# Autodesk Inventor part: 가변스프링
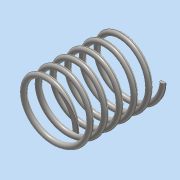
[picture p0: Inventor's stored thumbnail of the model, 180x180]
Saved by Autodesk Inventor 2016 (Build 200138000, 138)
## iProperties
Created: 2018-11
Part Number: 가변스프링
Material: 스테인레스 스틸
Document SubType Name: Modeling
Designer: 공506_39
Density: 8 g/cm^3
Appearance: 반연마
Mass: 84.1985 g
Surface Area: 106.476 cm^2
Volume: 10.5248 cm^3
Author: 공506_39
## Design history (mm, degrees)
sketch "스케치2"
  geometry: L1 (0, 0)-(22.5, 0); L2 (22.5, 0)-(22.5, 67.25); L3 (22.5, 67.25)-(0, 67.25); L4 (0, 67.25)-(0, 0); C1 r 2 at (22.5, 0)
  constraints: 8 end point, 2 parallel, 1 centre point, 1 coincident, 1 horizontal, 1 perpendicular
  dimensions: "d11" = 67.25 distance of L3.end L1.start (derived); "d12" = 45 diameter of L2 L4; "d13" = 4 diameter of C1
feature "코일2" sketch "스케치2" pitch "d14" = 10; turns "d16" = 6; dims "d15" = 67.25 (= d11), "d17" = 0, angle "d18" = 90 deg, angle "d19" = 90 deg, "d20" = 0, "d21" = 0
sketch "스케치3"
  geometry: L1 (67.25, 33.07)-(0, 33.07); L2 (0, 33.07)-(0, -33.07); L3 (0, -33.07)-(67.25, -33.07); L4 (67.25, -33.07)-(67.25, 33.07); 2 further points
  constraints: 8 end point, 2 parallel, 1 coincident, 1 horizontal, 1 midpoint, 1 perpendicular
  dimensions: "d22" = 67.25 distance of L2.end L3.end (= d11); "d23" = 66.1391 distance of L3.end L1.start
extrude "돌출1" sketch "스케치3" stored distance "d24" = 60; taper "d25" = 0 deg
node "솔리드2"
